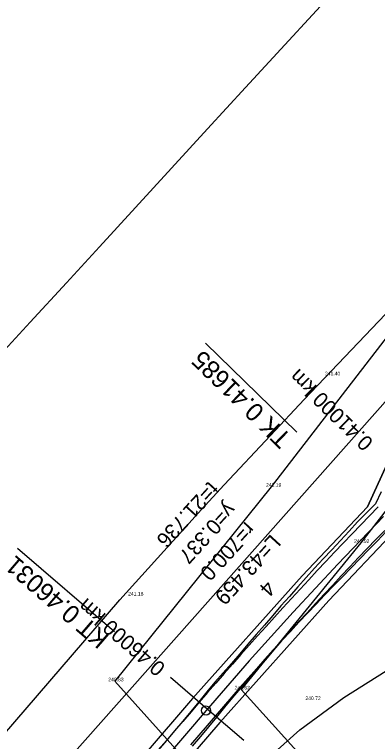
# Model space of a CAD drawing. Extents: x -555887 to -552101, y -1100251 to -1096546.
# Drawn here: x -555189.5 to -555129.5, y -1097961.6 to -1097841.4 of the extents above; entities that cross this region are included whole.
import ezdxf

# ---------------------------------------------------------------- set-up
doc = ezdxf.new("R2010")
doc.units = 0
for name, color, linetype in [('IP_návrh', 7, 'Continuous'), ('PARCELY_cesty', 7, 'Continuous'), ('PARCELY_ZP', 7, 'Continuous'), ('POLYGONY_SITUACE_PF', 7, 'Continuous'), ('POLYGONY_SITUACE_PF_POPISY', 7, 'Continuous'), ('POLYGONY_SITUACE_PO', 7, 'Continuous'), ('vrstevnice', 7, 'Continuous'), ('Výškopis', 7, 'Continuous'), ('ZSST', 7, 'Continuous'), ('zájem', 7, 'Continuous')]:
    doc.layers.add(name, color=color, linetype=linetype)

msp = doc.modelspace()

# ---------------------------------------------------------------- linework, layer by layer
for p, q in [((-555142.86, -1097910.43), (-555157.97, -1097895.72)), ((-555173.02, -1097943.41), (-555189.02, -1097929.67))]:
    msp.add_line(p, q)
at = {"layer": 'IP_návrh'}
msp.add_lwpolyline([(-555730.85, -1098494.64), (-555471.29, -1098211.98), (-555447.19, -1098191.79), (-555406.99, -1098193.78), (-555291.32, -1098130.27), (-555281.27, -1098119.66), (-555272.34, -1098101.41), (-555266.18, -1098052.11), (-555246.83, -1098023.92), (-555193.03, -1097978.41), (-554985.79, -1097744.7), (-554956.17, -1097701), (-554939.23, -1097656.04), (-554918.86, -1097601.97), (-554899.16, -1097585.1)], dxfattribs=at)
at = {"layer": 'PARCELY_cesty'}
for points in [[(-555043.66, -1097829.27), (-555070.96, -1097860.03), (-555099.18, -1097889.93), (-555107.44, -1097898.42), (-555113.49, -1097901.26), (-555127.92, -1097915.65), (-555131.15, -1097922.79), (-555141.95, -1097934.18), (-555160.11, -1097954.47), (-555192.77, -1097992.48)], [(-555039.15, -1097833.22), (-555066.53, -1097864.08), (-555094.85, -1097894.08), (-555126.36, -1097926.46), (-555137.53, -1097938.24), (-555155.6, -1097958.43), (-555188.3, -1097996.49)], [(-555131.15, -1097922.79), (-555127.92, -1097915.65), (-555113.49, -1097901.26), (-555107.44, -1097898.42)]]:
    msp.add_lwpolyline(points, dxfattribs=at)
at = {"layer": 'PARCELY_ZP'}
msp.add_lwpolyline([(-555445.24, -1098173.52), (-555417.39, -1098184.68), (-555381.15, -1098170.85), (-555299.54, -1098123.63), (-555285.35, -1098108), (-555279.05, -1098060.74), (-555272.16, -1098043.88), (-555262.31, -1098025.87), (-555247.78, -1098012.9), (-555216.95, -1097989.98), (-555203.13, -1097974.15), (-555172.13, -1097938.12), (-555158.62, -1097923.19), (-555154.87, -1097919.14), (-555147.19, -1097910.97), (-555141.65, -1097905.03), (-555123.73, -1097886.21), (-555084.65, -1097845.81), (-554996.25, -1097738.07)], dxfattribs=at)
at = {"layer": 'POLYGONY_SITUACE_PF'}
for p, q in [((-555157.65, -1097956.22), (-555163.72, -1097951)), ((-555151.59, -1097961.43), (-555157.65, -1097956.22))]:
    msp.add_line(p, q, dxfattribs=at)
at = {"layer": 'POLYGONY_SITUACE_PO'}
for p, q in [((-555128.87, -1097920.31), (-555129.82, -1097922.29)), ((-555129.82, -1097922.29), (-555131.31, -1097923.75)), ((-555129.36, -1097922.74), (-555130.82, -1097924.23)), ((-555128.53, -1097924.38), (-555136.04, -1097932.23)), ((-555131.31, -1097923.75), (-555132.78, -1097925.24)), ((-555130.82, -1097924.23), (-555132.27, -1097925.74)), ((-555132.78, -1097925.24), (-555134.2, -1097926.77)), ((-555132.27, -1097925.74), (-555133.71, -1097927.24)), ((-555134.2, -1097926.77), (-555135.61, -1097928.32)), ((-555128.3, -1097926.67), (-555129.75, -1097928.16)), ((-555128.3, -1097926.67), (-555129.75, -1097928.16)), ((-555128.09, -1097926.87), (-555129.52, -1097928.38)), ((-555133.71, -1097927.24), (-555135.16, -1097928.75)), ((-555135.61, -1097928.32), (-555137.03, -1097929.86)), ((-555135.16, -1097928.75), (-555136.59, -1097930.27)), ((-555129.75, -1097928.16), (-555131.19, -1097929.66)), ((-555129.75, -1097928.16), (-555131.19, -1097929.66)), ((-555129.52, -1097928.38), (-555130.96, -1097929.88)), ((-555137.03, -1097929.86), (-555138.46, -1097931.38)), ((-555136.59, -1097930.27), (-555138.03, -1097931.79)), ((-555131.19, -1097929.66), (-555132.62, -1097931.16)), ((-555131.19, -1097929.66), (-555132.62, -1097931.16)), ((-555130.96, -1097929.88), (-555132.41, -1097931.36)), ((-555138.46, -1097931.38), (-555139.9, -1097932.9)), ((-555132.62, -1097931.16), (-555134.05, -1097932.67)), ((-555132.62, -1097931.16), (-555134.05, -1097932.67)), ((-555132.41, -1097931.36), (-555133.86, -1097932.86)), ((-555136.04, -1097932.23), (-555143.44, -1097940.19)), ((-555139.9, -1097932.9), (-555141.3, -1097934.45)), ((-555138.03, -1097931.79), (-555139.46, -1097933.31)), ((-555134.05, -1097932.67), (-555135.48, -1097934.18)), ((-555134.05, -1097932.67), (-555135.48, -1097934.18)), ((-555133.86, -1097932.86), (-555135.3, -1097934.35)), ((-555139.46, -1097933.31), (-555140.88, -1097934.84)), ((-555141.3, -1097934.45), (-555142.7, -1097936)), ((-555140.88, -1097934.84), (-555142.3, -1097936.37)), ((-555135.48, -1097934.18), (-555136.9, -1097935.7)), ((-555135.48, -1097934.18), (-555136.9, -1097935.7)), ((-555135.3, -1097934.35), (-555136.75, -1097935.84)), ((-555142.7, -1097936), (-555144.08, -1097937.57)), ((-555142.3, -1097936.37), (-555143.72, -1097937.91)), ((-555136.9, -1097935.7), (-555138.32, -1097937.22)), ((-555136.9, -1097935.7), (-555138.32, -1097937.22)), ((-555136.75, -1097935.84), (-555138.19, -1097937.34)), ((-555144.08, -1097937.57), (-555145.46, -1097939.14)), ((-555138.32, -1097937.22), (-555139.73, -1097938.74)), ((-555138.32, -1097937.22), (-555139.73, -1097938.74)), ((-555138.19, -1097937.34), (-555139.63, -1097938.84)), ((-555143.72, -1097937.91), (-555145.13, -1097939.45)), ((-555139.73, -1097938.74), (-555141.14, -1097940.27)), ((-555139.73, -1097938.74), (-555141.14, -1097940.27)), ((-555139.63, -1097938.84), (-555141.05, -1097940.35)), ((-555145.46, -1097939.14), (-555146.83, -1097940.72)), ((-555145.13, -1097939.45), (-555146.53, -1097940.99)), ((-555143.44, -1097940.19), (-555150.71, -1097948.26)), ((-555146.83, -1097940.72), (-555148.18, -1097942.31)), ((-555146.53, -1097940.99), (-555147.93, -1097942.54)), ((-555141.14, -1097940.27), (-555142.54, -1097941.81)), ((-555141.14, -1097940.27), (-555142.54, -1097941.81)), ((-555141.05, -1097940.35), (-555142.49, -1097941.85)), ((-555148.18, -1097942.31), (-555149.56, -1097943.89)), ((-555147.93, -1097942.54), (-555149.33, -1097944.09)), ((-555142.54, -1097941.81), (-555143.94, -1097943.34)), ((-555142.54, -1097941.81), (-555143.94, -1097943.34)), ((-555142.49, -1097941.85), (-555143.9, -1097943.37)), ((-555143.94, -1097943.34), (-555145.33, -1097944.88)), ((-555143.94, -1097943.34), (-555145.33, -1097944.88)), ((-555143.9, -1097943.37), (-555145.33, -1097944.88)), ((-555149.56, -1097943.89), (-555150.92, -1097945.48)), ((-555149.33, -1097944.09), (-555150.72, -1097945.65)), ((-555145.33, -1097944.88), (-555146.73, -1097946.43)), ((-555145.33, -1097944.88), (-555146.73, -1097946.43)), ((-555145.38, -1097944.94), (-555146.68, -1097946.47)), ((-555145.33, -1097944.88), (-555145.38, -1097944.94)), ((-555150.92, -1097945.48), (-555152.27, -1097947.06)), ((-555150.72, -1097945.65), (-555152.11, -1097947.21)), ((-555152.27, -1097947.06), (-555153.64, -1097948.65)), ((-555152.11, -1097947.21), (-555153.49, -1097948.77)), ((-555146.73, -1097946.43), (-555148.11, -1097947.98)), ((-555146.73, -1097946.43), (-555148.11, -1097947.98)), ((-555146.68, -1097946.47), (-555148.03, -1097948.05)), ((-555150.71, -1097948.26), (-555157.85, -1097956.45)), ((-555148.11, -1097947.98), (-555149.49, -1097949.53)), ((-555148.11, -1097947.98), (-555149.49, -1097949.53)), ((-555148.03, -1097948.05), (-555149.38, -1097949.63)), ((-555153.64, -1097948.65), (-555155.03, -1097950.21)), ((-555153.49, -1097948.77), (-555154.87, -1097950.34)), ((-555149.49, -1097949.53), (-555150.87, -1097951.09)), ((-555149.49, -1097949.53), (-555150.87, -1097951.09)), ((-555149.38, -1097949.63), (-555150.75, -1097951.19)), ((-555155.03, -1097950.21), (-555156.4, -1097951.78)), ((-555154.87, -1097950.34), (-555156.25, -1097951.92)), ((-555156.4, -1097951.78), (-555157.74, -1097953.38)), ((-555156.25, -1097951.92), (-555157.61, -1097953.49)), ((-555150.87, -1097951.09), (-555152.24, -1097952.65)), ((-555150.87, -1097951.09), (-555152.24, -1097952.65)), ((-555150.75, -1097951.19), (-555152.14, -1097952.74)), ((-555157.74, -1097953.38), (-555159.06, -1097955)), ((-555152.24, -1097952.65), (-555153.61, -1097954.21)), ((-555152.24, -1097952.65), (-555153.61, -1097954.21)), ((-555152.14, -1097952.74), (-555153.49, -1097954.31)), ((-555157.61, -1097953.49), (-555158.98, -1097955.07)), ((-555153.61, -1097954.21), (-555154.97, -1097955.78)), ((-555153.61, -1097954.21), (-555154.97, -1097955.78)), ((-555153.49, -1097954.31), (-555154.8, -1097955.92)), ((-555159.06, -1097955), (-555160.38, -1097956.62)), ((-555158.98, -1097955.07), (-555160.34, -1097956.65)), ((-555154.97, -1097955.78), (-555156.33, -1097957.36)), ((-555154.97, -1097955.78), (-555156.33, -1097957.36)), ((-555157.85, -1097956.45), (-555190.53, -1097994.49)), ((-555160.38, -1097956.62), (-555161.7, -1097958.23)), ((-555160.34, -1097956.65), (-555161.69, -1097958.24)), ((-555154.8, -1097955.92), (-555156.12, -1097957.54)), ((-555156.33, -1097957.36), (-555157.68, -1097958.94)), ((-555156.33, -1097957.36), (-555157.68, -1097958.94)), ((-555156.12, -1097957.54), (-555157.43, -1097959.15)), ((-555161.7, -1097958.23), (-555163.05, -1097959.82)), ((-555161.69, -1097958.24), (-555163.05, -1097959.82)), ((-555157.68, -1097958.94), (-555159.04, -1097960.52)), ((-555157.68, -1097958.94), (-555159.04, -1097960.52)), ((-555157.43, -1097959.15), (-555158.78, -1097960.74)), ((-555163.05, -1097959.82), (-555164.41, -1097961.4)), ((-555163.05, -1097959.82), (-555164.41, -1097961.4)), ((-555163.05, -1097959.82), (-555163.05, -1097959.82)), ((-555159.04, -1097960.52), (-555160.4, -1097962.1)), ((-555159.04, -1097960.52), (-555160.4, -1097962.1)), ((-555164.41, -1097961.4), (-555165.78, -1097962.96)), ((-555164.41, -1097961.4), (-555165.77, -1097962.98)), ((-555164.41, -1097961.4), (-555164.41, -1097961.4)), ((-555158.78, -1097960.74), (-555160.13, -1097962.32))]:
    msp.add_line(p, q, dxfattribs=at)
msp.add_circle((-555157.85, -1097956.45), 0.75, dxfattribs=at)
at = {"layer": 'vrstevnice'}
for points in [[(-555135.05, -1097954.3), (-555117.49, -1097943.2), (-555102.19, -1097934.92), (-555084.78, -1097927.9), (-555072.98, -1097924.53), (-555046.02, -1097921.02)], [(-555168.18, -1097982.8), (-555142.35, -1097959.63), (-555135.05, -1097954.3)]]:
    msp.add_lwpolyline(points, dxfattribs=at)
at = {"layer": 'ZSST'}
for points in [[(-554818.66, -1098023.84), (-554825.46, -1098015.75), (-554864.2, -1097976.67), (-554889.06, -1097951.5), (-554935.3, -1097905.58), (-554964.9, -1097875.33), (-555000.7, -1097839.68), (-555033.41, -1097808.11), (-555044.89, -1097796.41), (-555060.34, -1097812.56), (-555089.55, -1097845.73), (-555113.34, -1097875.73), (-555147.08, -1097919.45), (-555172.92, -1097951.62), (-555118.56, -1098012.18)], [(-555033.41, -1097808.11), (-555048.23, -1097824.92), (-555074.97, -1097855.84), (-555100.24, -1097887.4), (-555132.27, -1097928.73), (-555152.04, -1097952.97), (-555107.98, -1098001.77), (-555074.22, -1098039.84), (-555011.02, -1098111.48), (-555060.47, -1098145.79)]]:
    msp.add_lwpolyline(points, dxfattribs=at)
at = {"layer": 'zájem'}
for points in [[(-555026.18, -1097717.1), (-555075.78, -1097771.09), (-555077.01, -1097772.5), (-555116.5, -1097815.51), (-555133.76, -1097834.29), (-555151.33, -1097853.41), (-555157.63, -1097860.26), (-555175.49, -1097879.78), (-555180.94, -1097885.71), (-555186.93, -1097892.2), (-555199.75, -1097906.11), (-555206.3, -1097913.32), (-555225.19, -1097933.77), (-555238.64, -1097948.52), (-555252.57, -1097963.73)], [(-555252.57, -1097963.73), (-555238.64, -1097948.52), (-555225.19, -1097933.77), (-555206.3, -1097913.32), (-555199.75, -1097906.11), (-555186.93, -1097892.2), (-555180.94, -1097885.71), (-555175.49, -1097879.78), (-555157.63, -1097860.26), (-555151.33, -1097853.41), (-555133.76, -1097834.29), (-555116.5, -1097815.51), (-555077.01, -1097772.5), (-555075.78, -1097771.09), (-555026.18, -1097717.1)]]:
    msp.add_lwpolyline(points, dxfattribs=at)

# ---------------------------------------------------------------- texts
for s, height, rotation, p in [('TK 0.41685', 3, 135.7741, (-555143.55, -1097911.15)), ('t=21.736', 2.5, 227.5527, (-555157.38, -1097918.39)), ('y=0.337', 2.5, 227.5527, (-555154.46, -1097921.87)), ('r=700.0', 2.5, 227.5527, (-555151.31, -1097925.09)), ('L=43.459', 2.5, 227.5527, (-555147.11, -1097927.16)), ('KT 0.46031', 3, 139.3313, (-555173.67, -1097944.17)), ('4', 2.5, 227.5527, (-555147.97, -1097934.77))]:
    msp.add_text(s, height=height, rotation=rotation).set_placement(p)
at = {"layer": 'POLYGONY_SITUACE_PF_POPISY'}
for s, rotation, p in [('0.41000 km', 135.7741, (-555130.04, -1097911.96)), ('0.46000 km', 139.3062, (-555164.39, -1097949.1))]:
    msp.add_text(s, height=2.5, rotation=rotation, dxfattribs=at).set_placement(p)
at = {"layer": 'Výškopis'}
for s, p in [('241.40', (-555138.19, -1097901.03)), ('241.19', (-555147.94, -1097919.45)), ('240.92', (-555133.37, -1097928.73)), ('241.18', (-555170.74, -1097937.43)), ('240.83', (-555174.03, -1097951.62)), ('240.62', (-555153.14, -1097952.97)), ('240.72', (-555141.43, -1097954.73))]:
    msp.add_text(s, height=0.6, dxfattribs=at).set_placement(p)

doc.saveas('drawing.dxf')
